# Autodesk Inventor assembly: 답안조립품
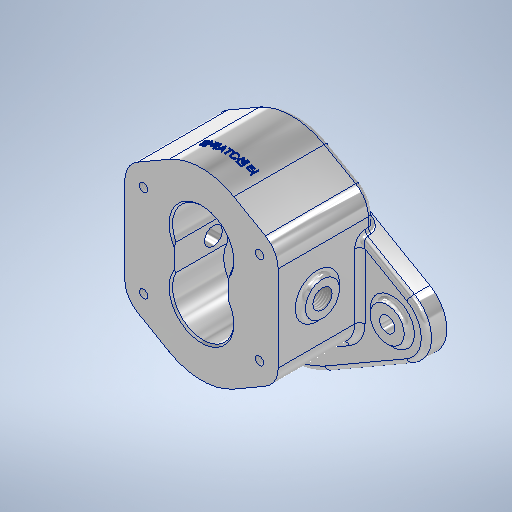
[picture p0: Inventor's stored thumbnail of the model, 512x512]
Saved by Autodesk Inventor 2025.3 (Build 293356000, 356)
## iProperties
Created: 2025-11
Part Number: 답안조립품
Document SubType Name: Assembly
Designer: PC-04
Author: PC-04
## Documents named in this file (2)
- C:\Users\PC-04\Desktop\751103V1010\답안조립품.iam
- C:\Users\PC-04\Desktop\751103V1010\본체.ipt
